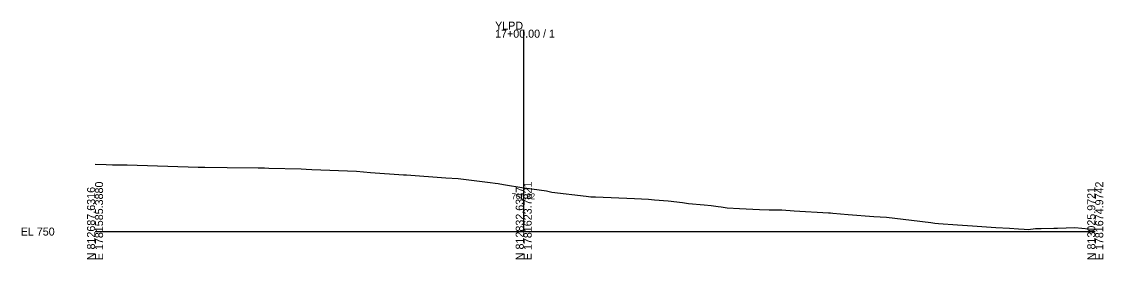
# Model space of a CAD drawing. Extents: x -26 to 353, y -10 to 9080.
# Drawn here: x -25.7 to 352.8, y 6990.3 to 7073.4 of the extents above; entities that cross this region are included whole.
import ezdxf

# ---------------------------------------------------------------- set-up
doc = ezdxf.new("R2010")
doc.units = 0
for name, color, linetype in [('Exist Cross Section Cell', 7, 'Continuous'), ('Exist XS Center Line Elevation Label', 7, 'Continuous'), ('Exist XS Ground Line', 7, 'Continuous')]:
    doc.layers.add(name, color=color, linetype=linetype)

msp = doc.modelspace()

# ---------------------------------------------------------------- linework, layer by layer
at = {"layer": 'Exist Cross Section Cell'}
for p, q in [((150, 7000), (150, 7070.56)), ((0, 7000), (150, 7000)), ((150, 7000), (350, 7000))]:
    msp.add_line(p, q, dxfattribs=at)
at = {"layer": 'Exist XS Ground Line'}
for p, q in [((0, 7023.52), (3.89, 7023.42)), ((3.89, 7023.42), (6.12, 7023.37)), ((6.12, 7023.37), (7.39, 7023.33)), ((7.39, 7023.33), (11.22, 7023.29)), ((11.22, 7023.29), (36.06, 7022.54)), ((36.06, 7022.54), (38.41, 7022.46)), ((38.41, 7022.46), (46.28, 7022.36)), ((46.28, 7022.36), (57.03, 7022.27)), ((57.03, 7022.27), (59.31, 7022.25)), ((59.31, 7022.25), (60.79, 7022.21)), ((60.79, 7022.21), (72.11, 7021.91)), ((72.11, 7021.91), (73.91, 7021.8)), ((73.91, 7021.8), (75.89, 7021.7)), ((75.89, 7021.7), (91.53, 7021.12)), ((91.53, 7021.12), (96.41, 7020.69)), ((96.41, 7020.69), (107.99, 7019.88)), ((107.99, 7019.88), (109.02, 7019.8)), ((109.02, 7019.8), (122.7, 7018.76)), ((122.7, 7018.76), (127.08, 7018.51)), ((127.08, 7018.51), (138.25, 7017.19)), ((138.25, 7017.19), (140, 7016.92)), ((140, 7016.92), (141.02, 7016.82)), ((141.02, 7016.82), (142.93, 7016.44)), ((142.93, 7016.44), (150, 7015.32)), ((150, 7015.32), (150.31, 7015.27)), ((150.31, 7015.27), (157.97, 7014.2)), ((157.97, 7014.2), (159.85, 7013.83)), ((159.85, 7013.83), (171.85, 7012.36)), ((171.85, 7012.36), (173.47, 7012.2)), ((173.47, 7012.2), (175.13, 7012.09)), ((175.13, 7012.09), (188.8, 7011.58)), ((188.8, 7011.58), (193.72, 7011.29)), ((193.72, 7011.29), (195.74, 7011.15)), ((195.74, 7011.15), (200.58, 7010.8)), ((200.58, 7010.8), (205.54, 7010.14)), ((205.54, 7010.14), (207.64, 7009.86)), ((207.64, 7009.86), (213.19, 7009.34)), ((213.19, 7009.34), (215.65, 7009.09)), ((215.65, 7009.09), (218.01, 7008.75)), ((218.01, 7008.75), (219.04, 7008.66)), ((219.04, 7008.66), (221.16, 7008.29)), ((221.16, 7008.29), (225.48, 7008.1)), ((225.48, 7008.1), (232.53, 7007.73)), ((232.53, 7007.73), (235.87, 7007.6)), ((235.87, 7007.6), (240.35, 7007.55)), ((240.35, 7007.55), (244.6, 7007.3)), ((244.6, 7007.3), (256.69, 7006.58)), ((256.69, 7006.58), (257.4, 7006.52)), ((257.4, 7006.52), (258.13, 7006.47)), ((258.13, 7006.47), (263.52, 7005.95)), ((263.52, 7005.95), (272.5, 7005.33)), ((272.5, 7005.33), (276.99, 7005)), ((276.99, 7005), (279.91, 7004.67)), ((279.91, 7004.67), (285.67, 7004.03)), ((285.67, 7004.03), (292.41, 7003.2)), ((292.41, 7003.2), (293.9, 7002.99)), ((293.9, 7002.99), (295.09, 7002.87)), ((295.09, 7002.87), (301.79, 7002.42)), ((301.79, 7002.42), (307, 7002.05)), ((307, 7002.05), (315.25, 7001.44)), ((315.25, 7001.44), (319.95, 7001.24)), ((319.95, 7001.24), (323.1, 7001.02)), ((323.1, 7001.02), (325.12, 7000.88)), ((325.12, 7000.88), (326.48, 7000.78)), ((326.48, 7000.78), (329.1, 7001.04)), ((329.1, 7001.04), (330.05, 7001.12)), ((330.05, 7001.12), (331.08, 7001.13)), ((331.08, 7001.13), (335.5, 7001.15)), ((335.5, 7001.15), (336.83, 7001.19)), ((336.83, 7001.19), (342.8, 7001.42)), ((342.8, 7001.42), (347.72, 7000.95)), ((347.72, 7000.95), (350, 7000.84))]:
    msp.add_line(p, q, dxfattribs=at)

# ---------------------------------------------------------------- texts
at = {"layer": 'Exist Cross Section Cell'}
for s, p in [('YLPD', (140, 7070.56)), ('17+00.00 / 1', (140, 7067.76)), ('EL 750', (-26, 6998.6))]:
    msp.add_text(s, height=2.8, dxfattribs=at).set_placement(p)
for s, p in [('N 812687.6316', (0, 6990)), ('E 1781585.3880', (2.8, 6990)), ('N 812832.6347', (150, 6990)), ('E 1781623.7821', (152.8, 6990)), ('N 813025.9721', (350, 6990)), ('E 1781674.9742', (352.8, 6990))]:
    msp.add_text(s, height=2.8, rotation=90, dxfattribs=at).set_placement(p)
at = {"layer": 'Exist XS Center Line Elevation Label'}
msp.add_text('765.32', height=2, dxfattribs=at).set_placement((145.79, 7011.32))

doc.saveas('drawing.dxf')
